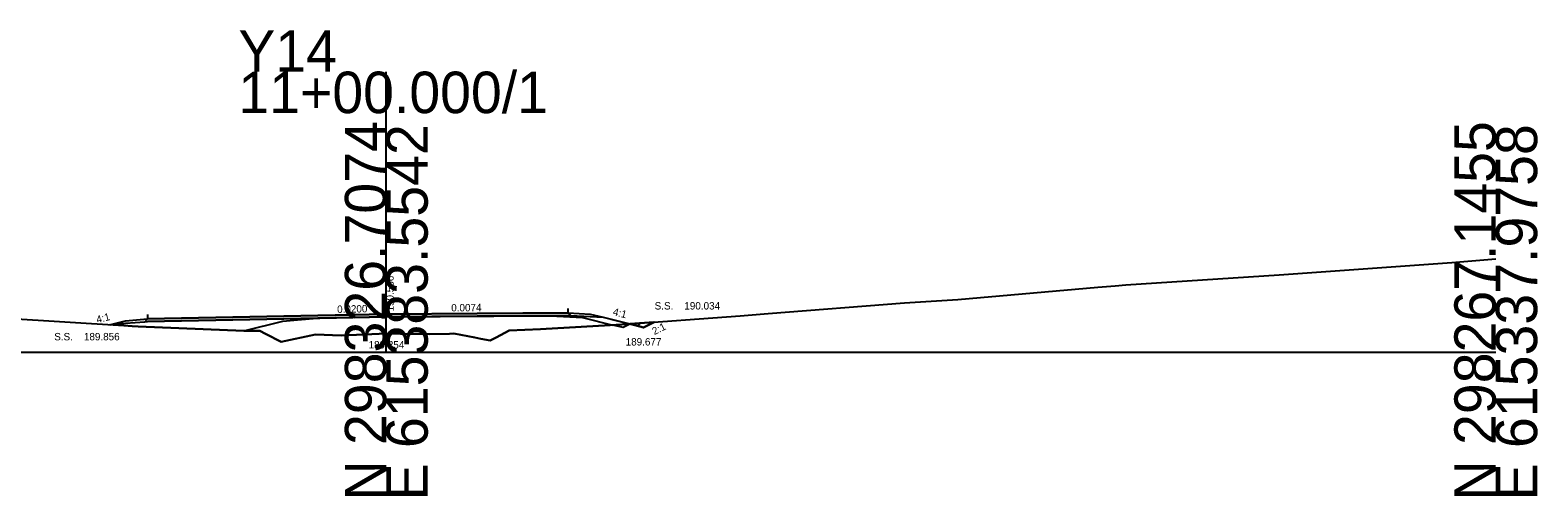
# Model space of a CAD drawing. Extents: x 517327 to 517505, y 114839 to 117370.
# Drawn here: x 517403.3 to 517505.2, y 117338.7 to 117370.1 of the extents above; entities that cross this region are included whole.
import ezdxf

# ---------------------------------------------------------------- set-up
doc = ezdxf.new("R2010")
doc.units = 0
for name, color, linetype in [('Exist XS Ground Line', 7, 'Continuous'), ('Old_Level_60', 7, 'Continuous'), ('Old_Level_63', 7, 'Continuous'), ('Prop XS Dump Level', 7, 'Continuous'), ('Prop XS Earthwork Shape', 7, 'Continuous'), ('Prop XS Elevation Labels', 7, 'Continuous'), ('Prop XS EOT Tick Mark', 7, 'Continuous'), ('Prop XS Finish Grade', 7, 'Continuous'), ('Prop XS Finish Grade Earthwork', 7, 'Continuous'), ('Prop XS Finish Grade Pavement', 7, 'Continuous'), ('Prop XS Hydro Elevations', 7, 'Continuous'), ('Prop XS Label Text', 7, 'Continuous'), ('Prop XS Pvmt Edge Slope', 7, 'Continuous'), ('Prop XS SE Text', 7, 'Continuous'), ('Prop XS Side Slope Text', 7, 'Continuous'), ('Prop XS Subgrade Earthwork', 7, 'Continuous'), ('Prop XS Suitable Common Exc Shape', 7, 'Continuous'), ('Scratch_Level_0', 7, 'Continuous')]:
    doc.layers.add(name, color=color, linetype=linetype)

msp = doc.modelspace()

# ---------------------------------------------------------------- linework, layer by layer
at = {"layer": 'Exist XS Ground Line'}
for p, q in [((517487.71, 117353.6), (517491.82, 117353.89)), ((517491.82, 117353.89), (517499.38, 117354.43)), ((517499.38, 117354.43), (517502.36, 117354.68)), ((517465.99, 117351.92), (517475.47, 117352.76)), ((517475.47, 117352.76), (517476.63, 117352.86)), ((517476.63, 117352.86), (517477.36, 117352.91)), ((517477.36, 117352.91), (517487.71, 117353.6)), ((517453.18, 117350.99), (517462.39, 117351.7)), ((517462.39, 117351.7), (517465.99, 117351.92)), ((517443.29, 117350.24), (517451.28, 117350.83)), ((517451.28, 117350.83), (517453.18, 117350.99)), ((517401.63, 117350.67), (517409.62, 117350.16)), ((517409.62, 117350.16), (517410.18, 117350.13)), ((517410.18, 117350.13), (517410.58, 117350.11)), ((517410.58, 117350.11), (517417.72, 117349.8)), ((517417.72, 117349.8), (517418.8, 117349.8)), ((517418.8, 117349.8), (517419.19, 117349.6)), ((517434.78, 117349.36), (517435.67, 117349.83)), ((517435.67, 117349.83), (517437.78, 117349.93)), ((517437.78, 117349.93), (517443.29, 117350.24)), ((517419.19, 117349.6), (517420.25, 117349.07)), ((517420.25, 117349.07), (517422.58, 117349.57)), ((517422.58, 117349.57), (517424.3, 117349.5)), ((517424.3, 117349.5), (517426.37, 117349.58)), ((517426.37, 117349.58), (517427.37, 117349.62)), ((517427.37, 117349.62), (517428.32, 117349.61)), ((517428.32, 117349.61), (517430.3, 117349.58)), ((517430.3, 117349.58), (517431.62, 117349.61)), ((517431.62, 117349.61), (517431.93, 117349.62)), ((517431.93, 117349.62), (517433.34, 117349.35)), ((517433.34, 117349.35), (517433.76, 117349.27)), ((517433.76, 117349.27), (517434.38, 117349.16)), ((517434.38, 117349.16), (517434.78, 117349.36))]:
    msp.add_line(p, q, dxfattribs=at)
at = {"layer": 'Old_Level_63'}
for p, q in [((517427.36, 117348.36), (517427.36, 117367.31)), ((517352.36, 117348.36), (517427.36, 117348.36)), ((517427.36, 117348.36), (517502.36, 117348.36))]:
    msp.add_line(p, q, dxfattribs=at)
at = {"layer": 'Prop XS Dump Level'}
for p, q in [((517411.22, 117350.61), (517427.36, 117350.93)), ((517427.36, 117350.93), (517439.65, 117351.02))]:
    msp.add_line(p, q, dxfattribs=at)
at = {"layer": 'Prop XS Earthwork Shape'}
for points in [[(517408.66, 117350.22), (517408.73, 117350.24), (517409.72, 117350.32), (517411.04, 117350.42), (517411.22, 117350.43), (517427.36, 117350.75), (517439.65, 117350.84), (517439.83, 117350.84), (517441.15, 117350.77), (517442.01, 117350.73), (517443.82, 117350.28), (517443.29, 117350.24), (517437.78, 117349.93), (517435.67, 117349.83), (517434.78, 117349.36), (517434.38, 117349.16), (517433.76, 117349.27), (517433.34, 117349.35), (517431.93, 117349.62), (517431.62, 117349.61), (517430.3, 117349.58), (517428.32, 117349.61), (517427.37, 117349.62), (517426.37, 117349.58), (517424.3, 117349.5), (517422.58, 117349.57), (517420.25, 117349.07), (517419.19, 117349.6), (517418.8, 117349.8), (517417.72, 117349.8), (517410.58, 117350.11), (517410.18, 117350.13), (517409.62, 117350.16)], [(517444.75, 117350.04), (517445.47, 117350.4), (517443.82, 117350.28)]]:
    msp.add_lwpolyline(points, close=True, dxfattribs=at)
at = {"layer": 'Prop XS EOT Tick Mark'}
for p, q in [((517411.22, 117350.91), (517411.22, 117350.61)), ((517439.65, 117351.02), (517439.65, 117351.33))]:
    msp.add_line(p, q, dxfattribs=at)
at = {"layer": 'Prop XS Finish Grade'}
for p, q in [((517439.65, 117351.02), (517441.15, 117350.94)), ((517441.15, 117350.94), (517442.01, 117350.73)), ((517408.73, 117350.24), (517409.72, 117350.49)), ((517409.72, 117350.49), (517411.22, 117350.61))]:
    msp.add_line(p, q, dxfattribs=at)
at = {"layer": 'Prop XS Finish Grade Earthwork'}
for p, q in [((517442.01, 117350.73), (517444.75, 117350.04)), ((517408.66, 117350.22), (517408.73, 117350.24)), ((517444.75, 117350.04), (517445.47, 117350.4))]:
    msp.add_line(p, q, dxfattribs=at)
at = {"layer": 'Prop XS Finish Grade Pavement'}
for p, q in [((517427.36, 117350.93), (517411.22, 117350.61)), ((517439.65, 117351.02), (517427.36, 117350.93))]:
    msp.add_line(p, q, dxfattribs=at)
at = {"layer": 'Prop XS Pvmt Edge Slope'}
for p, q in [((517439.65, 117351.02), (517439.83, 117350.84)), ((517411.04, 117350.42), (517411.22, 117350.61))]:
    msp.add_line(p, q, dxfattribs=at)
at = {"layer": 'Prop XS Subgrade Earthwork'}
for p, q in [((517427.36, 117350.75), (517411.22, 117350.43)), ((517439.65, 117350.84), (517427.36, 117350.75)), ((517439.65, 117350.84), (517439.83, 117350.84)), ((517439.83, 117350.84), (517441.15, 117350.77)), ((517441.15, 117350.77), (517442.01, 117350.73)), ((517408.73, 117350.24), (517409.72, 117350.32)), ((517409.72, 117350.32), (517411.04, 117350.42)), ((517411.04, 117350.42), (517411.22, 117350.43))]:
    msp.add_line(p, q, dxfattribs=at)
at = {"layer": 'Prop XS Suitable Common Exc Shape'}
for points in [[(517440.63, 117350.72), (517442.68, 117350.2), (517437.78, 117349.93), (517435.67, 117349.83), (517434.78, 117349.36), (517434.38, 117349.16), (517433.76, 117349.27), (517433.34, 117349.35), (517431.93, 117349.62), (517431.62, 117349.61), (517430.3, 117349.58), (517428.32, 117349.61), (517427.37, 117349.62), (517426.37, 117349.58), (517424.3, 117349.5), (517422.58, 117349.57), (517420.25, 117349.07), (517419.19, 117349.6), (517418.8, 117349.8), (517417.72, 117349.8), (517420.37, 117350.47), (517421.36, 117350.55), (517422.68, 117350.66), (517422.86, 117350.66), (517427.36, 117350.75), (517438.27, 117350.83), (517438.45, 117350.83), (517439.77, 117350.76)], [(517443.29, 117350.24), (517443.87, 117350.28), (517443.37, 117350.03), (517442.68, 117350.2)]]:
    msp.add_lwpolyline(points, close=True, dxfattribs=at)
at = {"layer": 'Scratch_Level_0'}
for p, q in [((517443.82, 117350.28), (517445.47, 117350.4)), ((517444.75, 117350.04), (517443.82, 117350.28)), ((517444.36, 117350.14), (517444.54, 117350.33)), ((517445.47, 117350.4), (517444.75, 117350.04))]:
    msp.add_line(p, q, dxfattribs=at)

# ---------------------------------------------------------------- texts
at = {"layer": 'Old_Level_60'}
msp.add_text('189.254', height=0.5, dxfattribs=at).set_placement((517426.16, 117348.62))
at = {"layer": 'Old_Level_63'}
for s, p in [('Y14', (517417.36, 117367.31)), ('11+00.000/1', (517417.36, 117364.51))]:
    msp.add_text(s, height=2.8, dxfattribs=at).set_placement(p)
for s, p in [('N 298326.7074', (517427.36, 117338.36)), ('E 615383.5542', (517430.16, 117338.36)), ('N 298267.1455', (517502.36, 117338.36)), ('E 615337.9758', (517505.16, 117338.36))]:
    msp.add_text(s, height=2.8, rotation=90, dxfattribs=at).set_placement(p)
at = {"layer": 'Prop XS Dump Level'}
for p in [(517441.15, 117350.93), (517409.72, 117350.48)]:
    msp.add_text('Case1', height=0.0122, dxfattribs=at).set_placement(p)
at = {"layer": 'Prop XS Elevation Labels'}
msp.add_text(' 190.566', height=0.5, rotation=90, dxfattribs=at).set_placement((517427.86, 117350.93))
at = {"layer": 'Prop XS Hydro Elevations'}
for s, p in [('S.S.    190.034', (517445.5, 117351.25)), ('S.S.    189.856', (517404.91, 117349.17))]:
    msp.add_text(s, height=0.5, dxfattribs=at).set_placement(p)
at = {"layer": 'Prop XS Label Text'}
msp.add_text('4:1', height=0.5, rotation=345.9638, dxfattribs=at).set_placement((517442.64, 117350.88))
at = {"layer": 'Prop XS SE Text'}
for s, rotation, p in [('0.0200', 1.1458, (517424.04, 117351.02)), ('0.0074', 0.4228, (517431.75, 117351.12))]:
    msp.add_text(s, height=0.5, rotation=rotation, dxfattribs=at).set_placement(p)
at = {"layer": 'Prop XS Side Slope Text'}
for s, rotation, p in [('4:1', 14.0362, (517407.82, 117350.32)), ('2:1', 26.5651, (517445.48, 117349.52))]:
    msp.add_text(s, height=0.5, rotation=rotation, dxfattribs=at).set_placement(p)
msp.add_text('189.677', height=0.5, dxfattribs=at).set_placement((517443.54, 117348.82))

doc.saveas('drawing.dxf')
